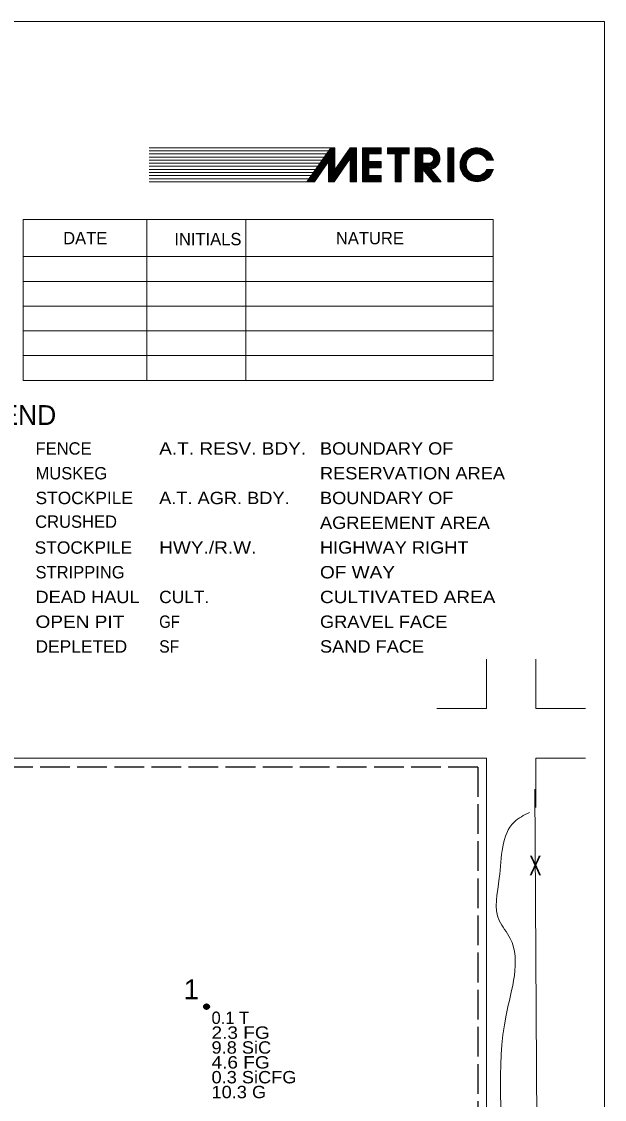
# Model space of a CAD drawing. Extents: x -496 to 480, y -450 to 700.
# Drawn here: x 214.3 to 450, y 264.4 to 700 of the extents above; entities that cross this region are included whole.
import ezdxf
from ezdxf.enums import TextEntityAlignment as Align

# ---------------------------------------------------------------- set-up
doc = ezdxf.new("R2010")
doc.units = 0
doc.header["$LTSCALE"] = 2
doc.linetypes.add('LONG_DASHED', pattern=[7.5, 6, -1.5])
for name, color, linetype, lineweight in [('1', 7, 'Continuous', 13), ('2', 7, 'Continuous', 35), ('3', 7, 'Continuous', 13)]:
    doc.layers.add(name, color=color, linetype=linetype, lineweight=lineweight)

msp = doc.modelspace()

# ---------------------------------------------------------------- linework, layer by layer
at = {"layer": '1'}
for p, q in [((339.376, 648.989), (265.976, 648.989)), ((329.726, 635.239), (339.376, 648.989)), ((340.976, 640.064), (347.226, 648.989)), ((349.726, 648.989), (347.226, 648.989)), ((349.726, 635.239), (349.726, 648.989)), ((362.226, 648.989), (362.226, 646.489)), ((379.026, 648.989), (373.476, 648.989)), ((338.501, 647.739), (265.976, 647.739)), ((337.626, 646.489), (265.976, 646.489)), ((336.751, 645.239), (265.976, 645.239)), ((340.676, 635.264), (347.226, 644.614)), ((347.226, 635.239), (347.226, 644.614)), ((354.726, 646.489), (354.726, 643.364)), ((362.226, 646.489), (365.351, 646.489)), ((367.851, 646.489), (370.976, 646.489)), ((376.601, 646.489), (379.151, 646.489)), ((376.601, 642.739), (376.601, 646.489)), ((335.876, 643.989), (265.976, 643.989)), ((335.001, 642.739), (265.976, 642.739)), ((334.126, 641.489), (265.976, 641.489)), ((332.776, 635.239), (338.476, 643.364)), ((338.476, 635.239), (338.476, 643.389)), ((354.726, 640.864), (354.726, 637.739)), ((376.601, 642.739), (379.151, 642.739)), ((379.801, 640.289), (383.951, 635.239)), ((402.426, 643.989), (405.076, 643.989)), ((333.251, 640.239), (265.976, 640.239)), ((332.376, 638.989), (265.976, 638.989)), ((331.501, 637.739), (265.976, 637.739)), ((330.626, 636.489), (265.976, 636.489)), ((376.601, 640.239), (380.726, 635.239)), ((376.601, 635.239), (376.601, 640.239)), ((402.426, 640.239), (405.101, 640.239)), ((329.726, 635.239), (265.976, 635.239)), ((329.726, 635.239), (332.776, 635.239)), ((338.476, 635.239), (340.676, 635.239)), ((349.726, 635.239), (347.226, 635.239)), ((352.226, 635.239), (359.726, 635.239)), ((380.726, 635.239), (383.951, 635.239)), ((404.983, 619.973), (214.983, 619.973)), ((214.983, 619.973), (214.983, 554.973)), ((264.983, 619.973), (264.983, 554.973)), ((304.983, 619.973), (304.983, 554.973)), ((404.983, 554.973), (404.983, 619.973)), ((214.983, 604.973), (404.983, 604.973)), ((214.983, 594.973), (404.983, 594.973)), ((214.983, 584.973), (404.983, 584.973)), ((214.983, 574.973), (404.983, 574.973)), ((214.983, 564.973), (404.983, 564.973)), ((214.983, 554.973), (404.983, 554.973)), ((402.281, 422.339), (402.281, 442.339)), ((422.281, 422.339), (422.281, 442.339)), ((402.281, 422.339), (382.281, 422.339)), ((422.281, 422.339), (442.281, 422.339)), ((422.281, 402.339), (442.281, 402.339)), ((422.281, 402.339), (422.281, 382.339))]:
    msp.add_line(p, q, dxfattribs=at)
for points in [[(449.983, -450.027), (449.983, 399.973), (449.983, 699.973), (-450.017, 699.973), (-450.017, 49.973), (-450.017, -450.027)], [(340.976, 640.039), (340.976, 648.989), (339.376, 648.989)], [(352.226, 635.239), (352.226, 648.989), (359.726, 648.989)], [(359.726, 648.989), (359.726, 646.489), (354.726, 646.489)], [(370.976, 646.489), (370.976, 648.989), (362.226, 648.989)], [(373.476, 648.989), (373.476, 635.239), (376.601, 635.239)], [(329.901, 635.339), (339.401, 648.889), (340.901, 648.889), (340.901, 639.839), (347.251, 648.839), (349.626, 648.889), (349.676, 635.339), (347.351, 635.314), (347.301, 644.789), (340.576, 635.339), (338.576, 635.314), (338.576, 643.539), (332.701, 635.339), (330.076, 635.314), (339.501, 648.739), (340.801, 648.739), (340.776, 639.664), (347.276, 648.664), (349.526, 648.739), (349.651, 635.564), (347.501, 635.464), (347.426, 644.989), (340.526, 635.489), (338.726, 635.439), (338.676, 643.764), (332.651, 635.464), (330.301, 635.439), (339.576, 648.539), (340.651, 648.564), (340.651, 639.489), (347.351, 648.489), (349.301, 648.564), (349.476, 635.739), (347.726, 635.639), (347.626, 645.314), (340.451, 635.714), (338.926, 635.639), (338.876, 644.139), (332.501, 635.689), (330.701, 635.639)], [(330.701, 635.639), (339.651, 648.239), (340.326, 648.264), (340.476, 639.239), (347.526, 648.239), (349.126, 648.289), (349.226, 635.939), (348.001, 635.939), (347.851, 645.664), (340.326, 635.989), (339.151, 635.864), (339.126, 644.464), (332.401, 635.939), (331.076, 635.839), (339.651, 647.914), (340.151, 647.914), (340.251, 638.889), (347.601, 647.964), (348.926, 648.014), (349.026, 636.164), (348.251, 636.139), (348.051, 646.014), (340.226, 636.239), (339.351, 636.089), (339.326, 644.789), (332.226, 636.164), (331.476, 636.064), (339.701, 647.664), (339.926, 647.689), (340.126, 638.764), (347.751, 647.839), (348.701, 647.739), (348.826, 636.364), (348.476, 636.364), (348.176, 646.314), (340.126, 636.464), (339.551, 636.339), (339.426, 645.114), (332.201, 636.339), (331.851, 636.289)], [(331.851, 636.289), (339.701, 647.264), (339.926, 638.564), (347.826, 647.614), (348.451, 647.589), (348.701, 636.589), (348.251, 646.639), (340.126, 636.689), (339.726, 636.589), (339.576, 645.539), (332.301, 636.639), (339.526, 646.714), (339.576, 645.814), (335.101, 640.239), (339.401, 646.164), (339.401, 645.914), (338.176, 644.289)], [(339.901, 638.414), (339.926, 636.839), (348.276, 646.889), (348.326, 647.439), (347.951, 647.439), (340.126, 638.539), (340.151, 637.314), (348.176, 647.064), (348.051, 647.214), (340.326, 638.539), (340.401, 637.839), (347.851, 646.839), (340.501, 638.639), (340.526, 638.389), (344.426, 642.914)], [(352.376, 648.914), (359.651, 648.864), (359.676, 646.614), (354.626, 646.589), (354.626, 643.289), (359.651, 643.289), (359.651, 640.989), (354.651, 640.939), (354.626, 637.614), (359.676, 637.639), (359.651, 635.339), (352.351, 635.314), (352.376, 648.789), (359.551, 648.739), (359.551, 646.764), (354.501, 646.714), (354.501, 643.214), (359.551, 643.164), (359.551, 641.114), (354.551, 641.064), (354.526, 637.439), (359.551, 637.514), (359.501, 635.439), (352.501, 635.439), (352.576, 648.639), (359.401, 648.564), (359.426, 646.914), (354.376, 646.839), (354.351, 643.064), (359.426, 643.039), (359.376, 641.289), (354.401, 641.239), (354.376, 637.239), (359.401, 637.339), (359.376, 635.589), (352.701, 635.614), (352.726, 648.439), (359.226, 648.414), (359.251, 647.064), (354.251, 647.039)], [(354.251, 647.039), (354.176, 642.864), (359.251, 642.864), (359.176, 641.439), (354.251, 641.389), (354.201, 637.064), (359.201, 637.114), (359.176, 635.739), (352.926, 635.814), (352.976, 648.214), (359.026, 648.239), (359.076, 647.289), (354.076, 647.214), (354.001, 642.689), (359.051, 642.664), (359.026, 641.639), (354.076, 641.564), (354.026, 636.864), (359.051, 636.939), (359.026, 635.989), (353.126, 636.039), (353.226, 647.989), (358.801, 648.039), (358.826, 647.464), (353.926, 647.389), (353.851, 642.489), (358.876, 642.539), (358.801, 641.814), (353.951, 641.689), (353.851, 636.714), (358.901, 636.764), (358.901, 636.214), (353.351, 636.214), (353.476, 647.714), (358.601, 647.889), (358.626, 647.639), (353.776, 647.514), (353.751, 642.364), (358.626, 642.389), (358.601, 642.014)], [(358.601, 642.014), (353.826, 641.864), (353.726, 636.564), (358.701, 636.639), (358.701, 636.389), (353.551, 636.439), (353.626, 641.989), (358.376, 642.164), (358.326, 642.289), (353.576, 642.264), (353.676, 647.564)], [(362.351, 648.864), (370.851, 648.889), (370.851, 646.639), (367.701, 646.639), (367.751, 635.414), (365.451, 635.314), (365.451, 646.564), (362.351, 646.589), (362.351, 648.764), (370.801, 648.789), (370.726, 646.789), (367.601, 646.764), (367.676, 635.539), (365.576, 635.414), (365.626, 646.739), (362.476, 646.739), (362.476, 648.639), (370.626, 648.639), (370.576, 646.989), (367.426, 646.864), (367.526, 635.739), (365.751, 635.614), (365.776, 646.864), (362.701, 646.939), (362.726, 648.439), (370.451, 648.489), (370.376, 647.114), (367.276, 646.989), (367.376, 635.914), (365.901, 635.789), (365.951, 647.064), (362.901, 647.114), (362.901, 648.264), (370.201, 648.289), (370.201, 647.364), (367.076, 647.189), (367.226, 636.114), (366.126, 635.989), (366.101, 647.264), (363.101, 647.314)], [(363.101, 647.314), (363.151, 648.089), (369.976, 648.164), (369.926, 647.489), (366.876, 647.364), (367.026, 636.339), (366.351, 636.239), (366.276, 647.439), (363.326, 647.514), (363.401, 647.939), (369.751, 648.039), (369.701, 647.714), (366.726, 647.539), (366.851, 636.564), (366.476, 636.489), (366.426, 647.664), (363.701, 647.664), (363.751, 647.839), (369.451, 647.914), (369.426, 647.814), (366.601, 647.664), (366.626, 636.689)], [(367.851, 646.489), (367.851, 635.239), (365.351, 635.239), (365.351, 646.489)], [(373.601, 648.914), (378.976, 648.889), (380.101, 648.739), (381.101, 648.364), (381.826, 647.789), (382.451, 647.189), (382.901, 646.414), (383.301, 645.389), (383.301, 644.439), (383.126, 643.214), (382.651, 642.314), (381.926, 641.489), (381.051, 640.889), (380.401, 640.639), (379.651, 640.389), (380.026, 639.714), (380.576, 639.189), (383.701, 635.339), (380.801, 635.314), (376.501, 640.464), (376.526, 635.339), (373.551, 635.314), (373.551, 648.864), (379.026, 648.789), (380.076, 648.639), (380.926, 648.314), (382.276, 647.214), (383.151, 645.364), (383.026, 643.314), (382.601, 642.464), (381.901, 641.614), (381.051, 640.989), (379.576, 640.464), (383.501, 635.414), (380.951, 635.439), (376.351, 640.739), (376.401, 635.489), (373.701, 635.439), (373.701, 648.739), (379.151, 648.664), (380.076, 648.489), (380.851, 648.189), (382.126, 647.139), (383.026, 645.389), (382.951, 643.539), (382.501, 642.564), (381.901, 641.739), (381.051, 641.114), (379.401, 640.614), (383.201, 635.564), (381.001, 635.564), (376.226, 640.889), (376.276, 635.614), (373.826, 635.539), (373.826, 648.614), (379.126, 648.489), (380.676, 648.089), (382.026, 647.139), (382.876, 645.439), (382.801, 643.664), (382.401, 642.664), (381.801, 641.889), (380.951, 641.189), (379.226, 640.764), (382.901, 635.689), (381.101, 635.689), (376.051, 641.064), (376.126, 635.789), (373.976, 635.689), (373.976, 648.439), (379.101, 648.364), (380.551, 647.989), (381.851, 647.089), (382.776, 645.439), (382.701, 643.764), (382.326, 642.889), (381.726, 642.064), (380.901, 641.339), (379.026, 640.939), (382.601, 635.789), (381.126, 635.814), (375.876, 641.239), (375.976, 635.939), (374.126, 635.864), (374.126, 648.239), (379.026, 648.239), (380.251, 647.914), (381.676, 647.014), (382.576, 645.414), (382.601, 643.914), (382.276, 642.989), (381.651, 642.214), (380.826, 641.514), (378.851, 641.064), (382.351, 635.939), (381.176, 635.989), (375.776, 641.514), (375.826, 636.089), (374.251, 636.014), (374.276, 648.039), (378.976, 648.114)], [(378.976, 648.114), (379.026, 648.114), (380.201, 647.764), (381.526, 646.939), (382.401, 645.489), (382.401, 643.964), (382.076, 643.114), (380.826, 641.764), (378.601, 641.264), (382.001, 636.114), (381.351, 636.114), (375.676, 641.789), (375.676, 636.264), (374.376, 636.189), (374.451, 647.864), (378.926, 647.939), (380.176, 647.689), (381.351, 646.914), (382.151, 645.414), (382.201, 644.014), (381.901, 643.214), (380.726, 641.989), (378.401, 641.389), (381.676, 636.314), (381.501, 636.189), (375.526, 642.064), (375.476, 636.414), (374.551, 636.339), (374.651, 647.739), (379.976, 647.614), (381.151, 646.914), (382.001, 645.414), (382.051, 644.139), (381.726, 643.339), (380.651, 642.139), (378.226, 641.589), (381.401, 636.464), (375.401, 642.364), (375.376, 636.614), (374.676, 636.539), (374.901, 647.589), (379.826, 647.414), (380.851, 646.889), (381.801, 645.439), (381.901, 644.389), (381.576, 643.539), (380.576, 642.414), (378.051, 641.739), (380.676, 637.364), (375.376, 642.614), (375.226, 636.739), (374.851, 636.739), (375.076, 647.339), (379.601, 647.314), (380.676, 646.839), (381.626, 645.414), (381.726, 644.464), (381.376, 643.589), (380.501, 642.589), (377.826, 641.864), (380.026, 638.189), (375.251, 642.889), (375.076, 636.939), (374.926, 636.989), (375.226, 647.189), (379.526, 647.139), (380.551, 646.714), (381.401, 645.414), (381.551, 644.614), (380.376, 642.739), (377.726, 642.039), (379.276, 639.239), (375.351, 643.039), (375.426, 646.989), (379.476, 646.989), (380.526, 646.639), (381.251, 645.489), (381.326, 644.614), (380.276, 642.914), (377.551, 642.239), (378.601, 640.139), (375.576, 643.139), (375.676, 646.839), (379.451, 646.839), (380.476, 646.514), (381.101, 645.414), (381.051, 644.489), (380.876, 645.464), (380.501, 646.039), (380.151, 646.339), (379.476, 646.514), (378.751, 646.639), (377.601, 646.614), (376.476, 646.614), (376.501, 642.714), (378.626, 642.664), (377.376, 642.339), (378.126, 640.764), (375.726, 643.164), (375.876, 646.714), (379.451, 646.714)], [(376.026, 646.614), (375.901, 643.214), (377.551, 641.614), (377.251, 642.364), (377.776, 642.614), (376.826, 642.614), (377.201, 642.164)], [(376.151, 646.564), (376.051, 643.314), (376.376, 643.064), (376.351, 646.564), (376.251, 643.389)], [(379.451, 646.714), (379.401, 646.739), (380.451, 646.289)], [(386.776, 648.839), (388.951, 648.864), (389.001, 635.364), (386.701, 635.364), (386.676, 648.739), (388.851, 648.764), (388.876, 635.489), (386.826, 635.439), (386.801, 648.614), (388.776, 648.639), (388.776, 635.664), (386.976, 635.589), (386.926, 648.464), (388.626, 648.464), (388.601, 635.764), (387.126, 635.764), (387.101, 648.364), (388.501, 648.364), (388.451, 635.939), (387.301, 635.964), (387.301, 648.214), (388.401, 648.214), (388.301, 636.089), (387.426, 636.089), (387.476, 648.064), (388.251, 648.039), (388.151, 636.214), (387.576, 636.214), (387.676, 647.914), (388.126, 647.889), (388.001, 636.339), (387.776, 636.389), (387.826, 647.764), (387.976, 647.714), (387.901, 636.539)], [(404.901, 644.089), (404.451, 645.189), (403.851, 646.164), (403.151, 646.914), (402.301, 647.639), (401.151, 648.289), (400.126, 648.614), (398.801, 648.814), (397.351, 648.689), (395.876, 648.339), (394.601, 647.639), (393.601, 646.764), (392.776, 645.664), (392.176, 644.564), (391.801, 642.964), (391.801, 641.264), (392.176, 639.789), (392.726, 638.564), (393.351, 637.739), (394.101, 637.014), (394.976, 636.389), (395.901, 635.914), (397.126, 635.489), (398.726, 635.389), (400.151, 635.589), (401.301, 635.989), (402.326, 636.564), (403.326, 637.414), (404.001, 638.264), (404.426, 639.139), (404.801, 640.064), (402.526, 640.089), (401.776, 638.989), (400.776, 638.289), (399.801, 637.814), (398.476, 637.564), (397.026, 637.839), (396.126, 638.289), (395.276, 638.939), (394.551, 639.939), (394.076, 641.189), (394.051, 642.814), (394.276, 643.889), (394.901, 644.889), (395.601, 645.614), (396.476, 646.164), (397.376, 646.489), (398.426, 646.614), (399.526, 646.489), (400.426, 646.214), (401.176, 645.764), (401.801, 645.239), (402.301, 644.664), (402.576, 644.139), (404.726, 644.164), (404.251, 645.214), (403.651, 646.164), (402.276, 647.489), (401.126, 648.114), (399.351, 648.614), (397.876, 648.564), (396.551, 648.339), (395.226, 647.814), (394.351, 647.264), (393.451, 646.339), (392.676, 645.139), (392.176, 643.939), (391.976, 642.239), (392.076, 640.689), (392.576, 639.164), (393.476, 637.864), (394.526, 636.864), (395.701, 636.164), (397.201, 635.639), (398.626, 635.514), (400.251, 635.764), (401.276, 636.089), (402.301, 636.789), (403.176, 637.439), (403.726, 638.164), (404.376, 639.239), (404.551, 639.964), (402.626, 639.989), (402.076, 639.064), (400.751, 638.139), (399.826, 637.689), (398.526, 637.389), (396.976, 637.739), (395.601, 638.439), (394.651, 639.639), (394.076, 640.764), (393.876, 642.139), (394.151, 643.989), (394.726, 644.964), (395.826, 646.014), (397.051, 646.539), (398.351, 646.789), (399.826, 646.614), (401.026, 646.064), (401.701, 645.614), (402.226, 645.014)], [(402.226, 645.014), (402.301, 645.014), (402.676, 644.239), (404.476, 644.264), (404.026, 645.314), (402.876, 646.664), (401.901, 647.489), (400.851, 648.089), (399.251, 648.514), (396.976, 648.264), (395.201, 647.614), (394.051, 646.639), (393.151, 645.614), (392.526, 644.239), (392.176, 642.439), (392.326, 640.539), (392.676, 639.489), (392.951, 638.864), (393.701, 637.864), (394.851, 636.839), (397.101, 635.814), (398.651, 635.664), (401.026, 636.164), (403.076, 637.564), (403.901, 638.814), (404.326, 639.814), (403.476, 639.789), (402.726, 639.839), (402.201, 638.889), (400.776, 637.964), (399.526, 637.414), (398.251, 637.264), (396.651, 637.714), (395.476, 638.364), (394.451, 639.714), (393.901, 640.864), (393.701, 642.264), (393.976, 643.889), (394.651, 645.264), (395.701, 646.214), (397.376, 646.789), (398.851, 646.914), (400.251, 646.614), (401.626, 645.914), (402.426, 645.164), (402.801, 644.439), (404.226, 644.414), (403.426, 645.739), (402.676, 646.614), (401.826, 647.314), (400.851, 647.939), (399.276, 648.314), (397.051, 648.089), (395.226, 647.364), (393.976, 646.314), (393.201, 645.414), (392.651, 643.839), (392.426, 642.514), (392.451, 641.239), (392.651, 640.089), (393.101, 639.039), (393.651, 638.239), (394.376, 637.564), (395.226, 636.839), (396.351, 636.314), (397.451, 635.914), (398.701, 635.839), (400.826, 636.364), (402.976, 637.639), (403.801, 638.964), (404.026, 639.714), (402.851, 639.664), (402.326, 638.814), (401.226, 638.164), (399.651, 637.239), (398.226, 637.114), (397.101, 637.389), (395.976, 637.889), (394.801, 638.989), (394.101, 640.014), (393.601, 641.664), (393.676, 643.264), (394.101, 644.689), (395.376, 646.214), (396.876, 646.764), (398.751, 647.064), (400.326, 646.764), (401.751, 646.089), (402.651, 645.189), (402.951, 644.539), (403.876, 644.614), (403.051, 645.989), (402.201, 646.789), (400.851, 647.739), (399.376, 648.189), (397.151, 647.889), (395.451, 647.239), (394.076, 646.164), (393.251, 645.039), (392.701, 643.014), (392.651, 641.564)], [(392.651, 641.564), (392.676, 641.614), (392.951, 639.914), (393.451, 638.964), (394.051, 638.214), (394.926, 637.289), (395.951, 636.764), (396.601, 636.389), (397.801, 636.039), (398.776, 635.989), (400.726, 636.464), (402.951, 637.739), (403.651, 639.064), (403.726, 639.564), (403.026, 639.539), (402.576, 638.814), (399.876, 637.114), (398.026, 637.014), (396.051, 637.664), (394.476, 639.139), (393.526, 641.439), (393.651, 643.889), (394.476, 645.514), (395.726, 646.539), (397.351, 646.989), (398.701, 647.239), (400.476, 646.939), (401.751, 646.339), (402.526, 645.664), (402.851, 645.114), (403.076, 644.739), (403.551, 644.789), (402.926, 645.989), (401.801, 646.914), (400.676, 647.639), (399.376, 648.039), (397.176, 647.789), (395.676, 647.164), (394.226, 646.139), (393.501, 645.039), (392.901, 643.314), (392.826, 641.639), (393.126, 639.989), (393.851, 638.689), (394.951, 637.514), (396.001, 636.989), (396.726, 636.564), (398.626, 636.139), (400.701, 636.614), (402.776, 637.864), (403.476, 639.064), (403.601, 639.464), (403.251, 639.389), (402.751, 638.739), (400.001, 637.014), (398.001, 636.889), (395.901, 637.564), (394.326, 639.064), (393.376, 641.464), (393.576, 643.939), (394.301, 645.589), (395.526, 646.689), (398.576, 647.339), (400.751, 647.089), (401.751, 646.489), (402.601, 645.914), (403.076, 645.039), (403.326, 644.914), (402.851, 645.939), (400.926, 647.289), (399.526, 647.889), (397.401, 647.714), (395.626, 647.039), (394.251, 646.039), (393.576, 644.889), (393.026, 643.239), (392.951, 641.714), (393.276, 640.314), (393.801, 639.139), (394.376, 638.339), (395.076, 637.639), (396.901, 636.764), (398.651, 636.314), (400.576, 636.789), (402.601, 637.914), (403.351, 639.139), (402.501, 638.339), (401.601, 637.789), (400.101, 636.864), (398.051, 636.764), (395.801, 637.439), (394.176, 639.064), (393.226, 641.539), (393.501, 644.014), (394.126, 645.639), (395.451, 646.739), (397.026, 647.189), (398.576, 647.489), (399.776, 647.389), (400.526, 647.289), (399.551, 647.639)], [(402.751, 638.439), (402.076, 637.814), (400.676, 637.089), (399.226, 636.639), (398.501, 636.639), (396.951, 636.914), (395.751, 637.364), (394.201, 638.764), (393.101, 641.589), (393.401, 643.964), (393.901, 645.289)], [(399.551, 647.639), (398.601, 647.639), (397.451, 647.489), (395.901, 647.064)], [(354.726, 640.864), (359.726, 640.864), (359.726, 643.364), (354.726, 643.364)], [(354.726, 637.739), (359.726, 637.739), (359.726, 635.239)], [(402.281, -402.333), (402.281, 402.339), (-402.391, 402.339)]]:
    msp.add_lwpolyline(points, dxfattribs=at)
msp.add_lwpolyline([(386.601, 635.239), (386.601, 648.989), (389.101, 648.989), (389.101, 635.239)], close=True, dxfattribs=at)
for centre, radius, start, end in [((379.076, 644.614), 4.375, 279.51602, 90.65478), ((398.476, 642.114), 6.875, 15.80251, 344.19749), ((379.051, 644.614), 1.875, 272.29061, 86.94712), ((398.476, 642.114), 4.375, 25.39292, 334.60708)]:
    msp.add_arc(centre, radius, start, end, dxfattribs=at)
at = {"layer": '2', "linetype": 'LONG_DASHED', "lineweight": 25}
for q in [(-292.391, 398.739), (398.852, 134.415)]:
    msp.add_line((398.852, 398.739), q, dxfattribs=at)
at = {"layer": '2'}
msp.add_circle((289.137, 301.926), 1, dxfattribs=at)
msp.add_spline([(289.126, 302.813), (289.856, 302.409), (290.008, 301.56), (289.323, 301.032), (288.514, 301.263), (288.227, 302.021), (288.474, 302.583), (289.047, 302.751), (289.721, 302.257), (289.705, 301.515), (289.188, 301.257), (288.665, 301.426), (288.441, 302.072), (289.025, 302.538), (289.463, 302.004), (289.424, 301.521), (288.795, 301.656), (288.941, 302.291), (289.233, 301.74)], degree=3, dxfattribs=at)
at = {"layer": '3'}
msp.add_line((423.111, 180.13), (421.865, 389.84), dxfattribs=at)
msp.add_spline([(419.648, 380.431), (413.553, 376.556), (407.457, 353.863), (407.457, 336.705), (411.89, 329.509), (413.553, 314.565), (410.228, 298.514), (408.565, 233.202), (408.011, 167.337), (415.769, 134.128), (414.661, 93.723)], degree=3, dxfattribs=at)

# ---------------------------------------------------------------- texts
at = {"layer": '1'}
for s, height, p in [('DATE', 5, (240.081, 609.973)), ('INITIALS', 5, (289.66, 609.584)), ('NATURE', 5, (355.16, 609.973)), ('LEGEND', 8, (206.378, 536.973))]:
    msp.add_text(s, height=height, dxfattribs=at).set_placement(p, align=Align.CENTER)
for s, p in [('FENCE', (219.983, 524.973)), ('MUSKEG', (219.983, 514.973)), ('CRUSHED', (219.856, 495.402)), ('STRIPPING', (219.983, 474.973))]:
    msp.add_text(s, height=5, dxfattribs=at).set_placement(p)
for s, width, p in [('A.T. RESV. BDY.', 1.15, (269.983, 524.973)), ('BOUNDARY OF', 1.1, (334.983, 524.973)), ('RESERVATION AREA', 1.1, (334.983, 514.973)), ('STOCKPILE', 1.05, (219.983, 504.973)), ('A.T. AGR. BDY.', 1.1, (269.983, 504.973)), ('BOUNDARY OF', 1.1, (334.983, 504.973)), ('AGREEMENT AREA', 1.1, (334.983, 494.973)), ('STOCKPILE', 1.05, (219.649, 484.941)), ('HWY./R.W.', 1.15, (269.983, 484.973)), ('HIGHWAY RIGHT', 1.1, (334.983, 484.973)), ('OF WAY', 1.15, (334.983, 474.973)), ('DEAD HAUL', 1.1, (219.983, 464.973)), ('CULT.', 1.05, (269.983, 464.973)), ('CULTIVATED AREA', 1.15, (334.983, 464.973)), ('OPEN PIT', 1.15, (219.983, 454.973)), ('GF', 0.9, (269.983, 454.973)), ('GRAVEL FACE', 1.1, (334.983, 454.973)), ('DEPLETED', 1.05, (219.983, 444.973)), ('SF', 0.95, (269.983, 444.973)), ('SAND FACE', 1.1, (334.983, 444.973))]:
    msp.add_text(s, height=5, dxfattribs=dict(at, width=width)).set_placement(p)
at = {"layer": '2', "width": 1.05}
msp.add_text('  1', height=8, dxfattribs=at).set_placement((286.136, 304.926), align=Align.RIGHT)
at = {"layer": '2'}
msp.add_text('0.1 T      ', height=5, dxfattribs=at).set_placement((291.137, 294.926))
for s, width, p in [('2.3 FG     ', 1.15, (291.137, 288.926)), ('9.8 SiC    ', 1.1, (291.137, 282.926)), ('4.6 FG     ', 1.15, (291.137, 276.926)), ('0.3 SiCFG  ', 1.1, (291.137, 270.926)), ('10.3 G     ', 1.1, (291.137, 264.926))]:
    msp.add_text(s, height=5, dxfattribs=dict(at, width=width)).set_placement(p)
at = {"layer": '3', "width": 0.7}
msp.add_text('X', height=8, dxfattribs=at).set_placement((422.042, 354.921), align=Align.CENTER)

doc.saveas('drawing.dxf')
